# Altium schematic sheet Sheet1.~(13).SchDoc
size A3; SheetNumber: 1; SheetTotal: 1
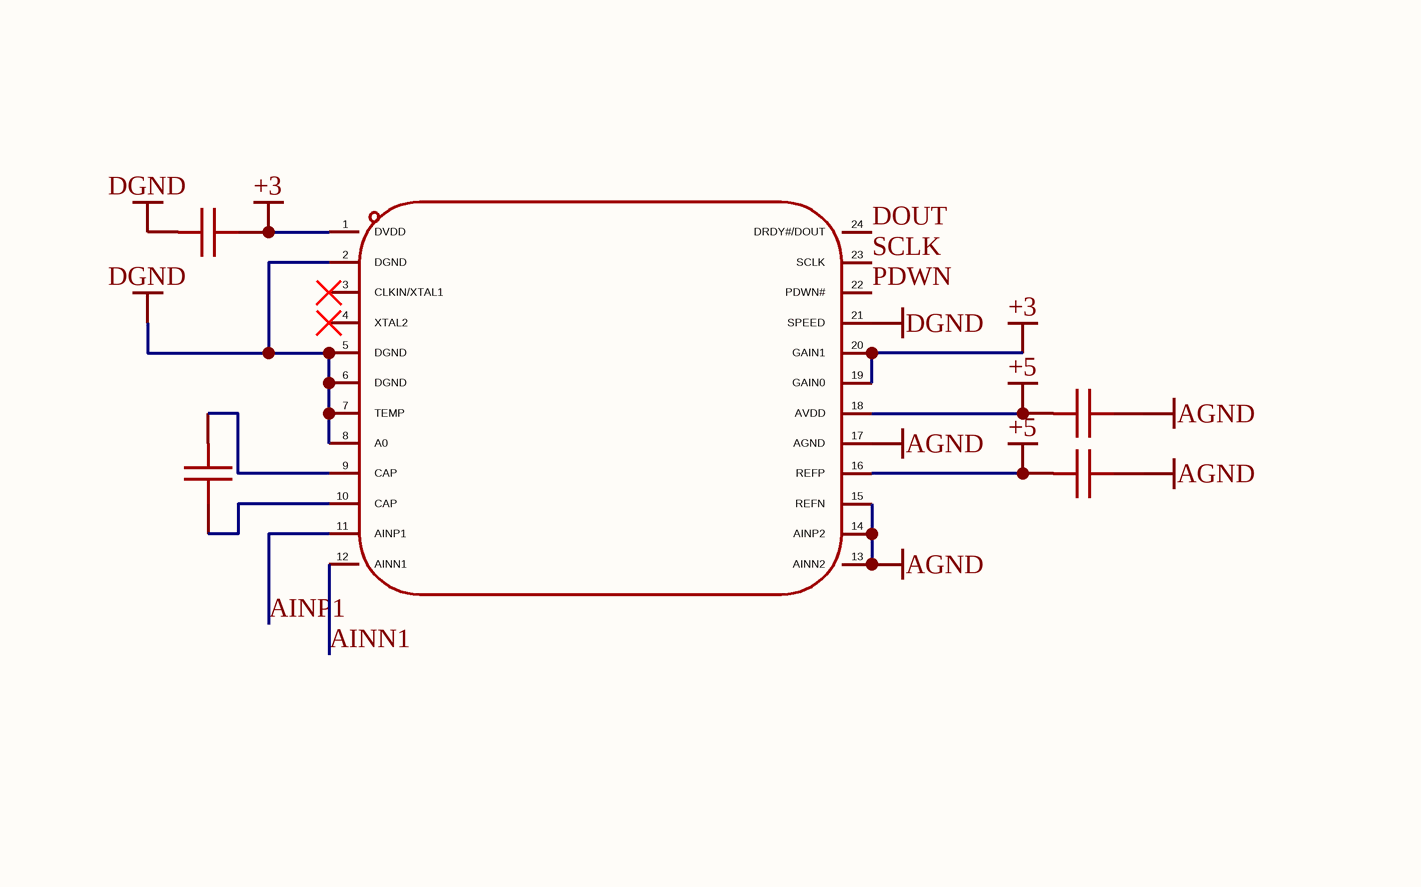
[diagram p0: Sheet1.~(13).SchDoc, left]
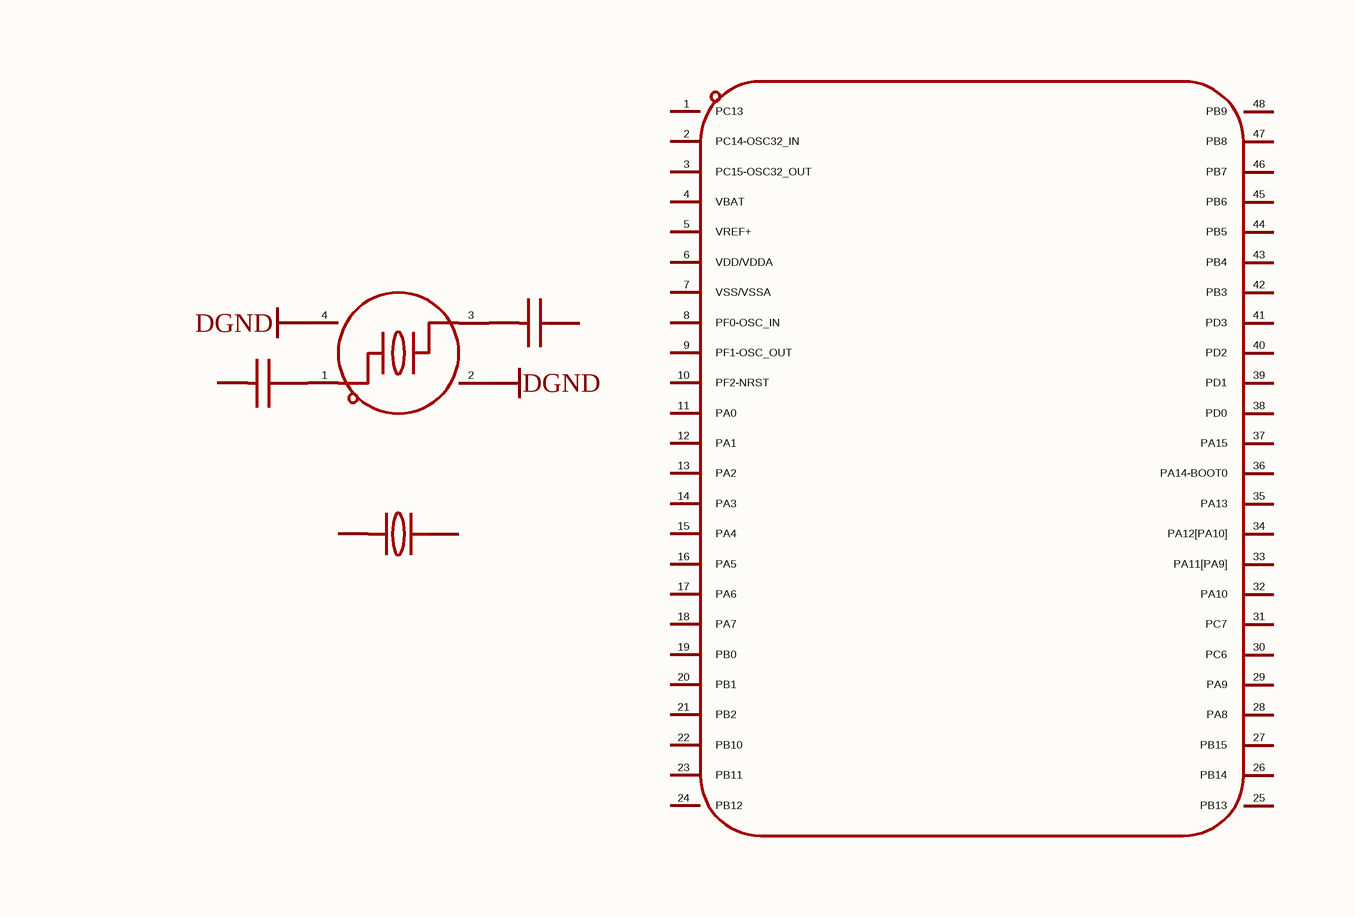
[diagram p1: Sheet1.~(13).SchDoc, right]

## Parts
(Parts that share a designator on the sheet are numbered #1, #2 ... from top to bottom, then left to right.)
C?#1  cga0603x7r104k500jt  [C0603]  (value not drawn)
C?#2  cga0603x7r104k500jt  [C0603]  (value not drawn)
C?#3  cga0603x7r104k500jt  [C0603]  (value not drawn)
C??#1  cc0402jrnpo9bn180  [C0402]  (value not drawn)
C??#2  cc0402jrnpo9bn180  [C0402]  (value not drawn)
C??#3  cga0603x7r104k500jt  [C0603]  (value not drawn)
U??#1  ads1232ipwr  [TSSOP-24_L7.8-W4.4-P0.65-LS6.4-BL]  (value not drawn)
U??#2  stm32g031c8t6  [LQFP-48_L7.0-W7.0-P0.50-LS9.0-BL]  (value not drawn)
U??#3  fc31m2-32.768-ntlnndtl  [CRYSTAL-SMD_L3.2-W1.5]  (value not drawn)
X??  x32258mob4si  [CRYSTAL-SMD_4P-L3.2-W2.5-BL]  (value not drawn)

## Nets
+3: C?#1.1 U??#1.1(DVDD) U??#1.19(GAIN0) U??#1.20(GAIN1)
+5: C?#2.2 C?#3.2 U??#1.16(REFP) U??#1.18(AVDD)
AGND: C?#2.1 C?#3.1 U??#1.13(AINN2) U??#1.14(AINP2) U??#1.15(REFN) U??#1.17(AGND)
DGND: C?#1.2 U??#1.2(DGND) U??#1.5(DGND) U??#1.6(DGND) U??#1.7(TEMP) U??#1.8(A0) U??#1.21(SPEED) X??.2(GND) X??.4(GND)
AINN1: U??#1.12(AINN1)
AINP1: U??#1.11(AINP1)
DOUT: U??#1.24(DRDY#/DOUT)
PDWN: U??#1.22(PDWN#)
SCLK: U??#1.23(SCLK)
NetC??#1_1: C??#1.1 X??.3
NetC??#2_2: C??#2.2 X??.1
NetC??#3_1: C??#3.1 U??#1.10(CAP)
NetC??#3_2: C??#3.2 U??#1.9(CAP)

Not connected (* = marked no-connect by the designer): C??#1 2; C??#2 1; U??#1 3(CLKIN/XTAL1)* 4(XTAL2)*; U??#2 1(PC13) 2(PC14-OSC32_IN) 3(PC15-OSC32_OUT) 4(VBAT) 5(VREF+) 6(VDD/VDDA) 7(VSS/VSSA) 8(PF0-OSC_IN) 9(PF1-OSC_OUT) 10(PF2-NRST) 11(PA0) 12(PA1) 13(PA2) 14(PA3) 15(PA4) 16(PA5) 17(PA6) 18(PA7) 19(PB0) 20(PB1) 21(PB2) 22(PB10) 23(PB11) 24(PB12) 25(PB13) 26(PB14) 27(PB15) 28(PA8) 29(PA9) 30(PC6) 31(PC7) 32(PA10) 33(PA11[PA9]) 34(PA12[PA10]) 35(PA13) 36(PA14-BOOT0) 37(PA15) 38(PD0) 39(PD1) 40(PD2) 41(PD3) 42(PB3) 43(PB4) 44(PB5) 45(PB6) 46(PB7) 47(PB8) 48(PB9); U??#3 1 2

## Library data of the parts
C?#1-C?#3 C??#3 = cga0603x7r104k500jt: 容值:100nF;精度:±10%;额定电压:50V;温度系数:X7R;; Manufacturer: HRE(芯声); AddInBom: yes; ModelId: ac125912035d415993ca9572d50418b1; ModelName: C0603_L1.6-W0.8-H0.8; ModelTransform: 62.992,31.496,0,0,0,0,0,0,0; Value: 100nF; Tolerance: ±10%; Voltage Rating: 50V; Temperature Coefficient: X7R
C??#1 C??#2 = cc0402jrnpo9bn180: 容值:18pF;精度:±5%;额定电压:50V;温度系数:NP0;; Manufacturer: YAGEO(国巨); AddInBom: yes; ModelId: 36a51122f27c49738f86b3bfa98863e0; ModelName: C0402_L1.0-W0.5-H0.5; ModelTransform: 39.37,19.685,0,0,0,0,0,0,0; Value: 18pF; Tolerance: ±5%; Voltage Rating: 50V; Temperature Coefficient: NP0
U??#1 = ads1232ipwr: 分辨率(位):24;采样率:10Hz;工作电压:2.7V~5.3V;接口类型:SPI;; Manufacturer: TI(德州仪器); AddInBom: yes; ModelId: 57e278220af748a2882c4abba4094eb9; ModelName: TSSOP-24_L7.8-W4.4-H1.0-LS6.4-P0.65; ModelTransform: 252.188,307.086,0,90,0,0,0,0,0; Resolution (Bits): 24; Sampling Rate: 10Hz; number of channels: 2; Interface: SPI; differential input: 是; Clock/Oscillator: 内置；外置; Clock Frequency: 4.9152MHz；200kHz~8MHz; Voltage Reference: 外置; Programmable Gain: 支持; Temperature Sensors: 内置; ADC architecture: Sigma-Delta; Data rate: 80Hz；10Hz; Quiescent Current (Iq): 1.3uA; Full-Scale Range(FSR): 39mV；1.25V；19.5mV；2.5V
U??#2 = stm32g031c8t6: CPU内核:ARM Cortex-M0+;CPU最大主频:64MHz;CPU位数:32 Bit;; Manufacturer: ST(意法半导体); AddInBom: yes; ModelId: 093be70396ff421eb2cdb946d5311efc; ModelName: LQFP-48_L7.0-W7.0-H1.4-LS9.0-P0.50; ModelTransform: 354.331,354.331,0,0,0,0,0,0,0; CPU Maximum Speed: 64MHz; Core Size: 32 Bit; Program Storage Size: 64KB; Program Memory Type: FLASH; RAM Size: 8KB; Number of I/O: 44; ADC (Bit): 12bit; Oscillator Type: 内置+外置; Voltage - Supply: 1.7V~3.6V
U??#3 = fc31m2-32.768-ntlnndtl: 晶振类型:贴片晶振;频率:32.768kHz;常温频差:±10ppm;负载电容:12.5pF;频率稳定度:±10ppm;; Manufacturer: HCI(杭晶); AddInBom: yes; ModelId: 762d7afc596f4558a373612390f4386d; ModelName: CRYSTAL-SMD_L3.2-W1.5-1; ModelTransform: 125.984,59.055,0,0,0,0,0,0,0; Normal temperature Frequency Tolerance: ±10ppm; Load Capacitance: 12.5pF; Equivalent Series Resistance(ESR): 70kΩ
X?? = x32258mob4si: 晶振类型:贴片晶振;频率:8MHz;常温频差:±10ppm;负载电容:12pF;频率稳定度:±20ppm;; Manufacturer: YXC(扬兴晶振); AddInBom: yes; ModelId: ff2dfd5650294453a14147960efe1838; ModelTransform: 125.984,98.425,0,0,0,0,0,0,0; Value: 8MHz; Normal temperature Frequency Tolerance: ±10ppm; Load Capacitance: 12pF; Frequency Stability: ±20ppm; Equivalent Series Resistance(ESR): 180Ω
